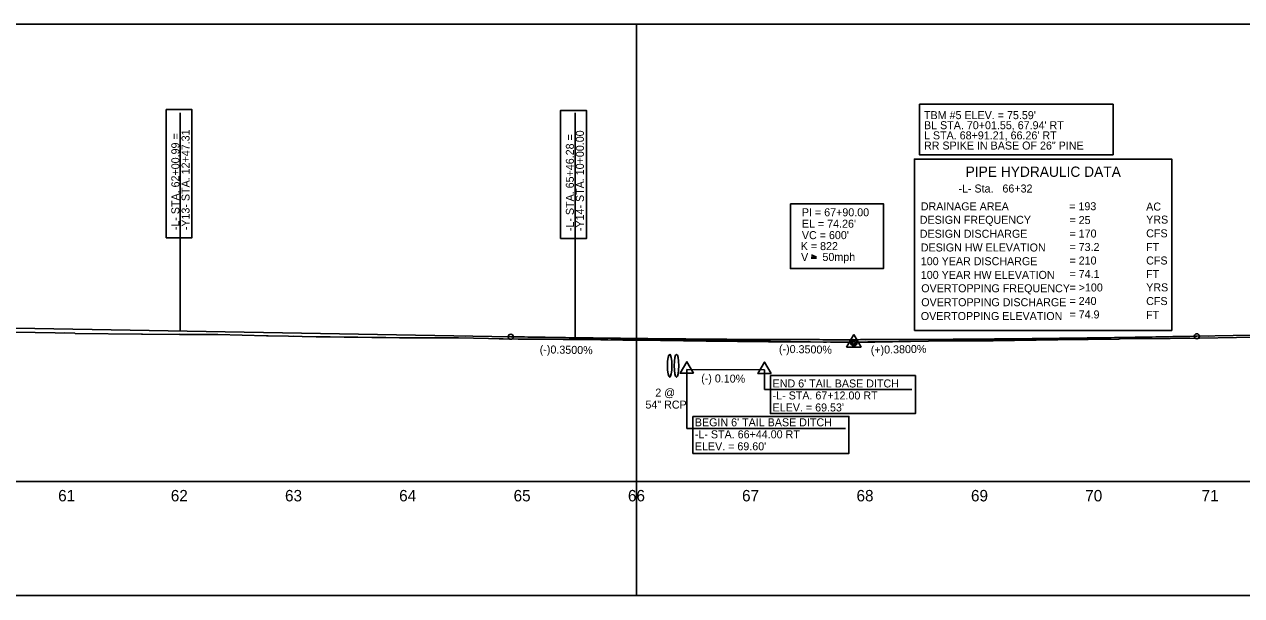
# Model space of a CAD drawing. Extents: x 2366464 to 2375718, y 801842 to 804354.
# Drawn here: x 2372383 to 2373447, y 803754 to 804254 of the extents above; entities that cross this region are included whole.
import ezdxf

# ---------------------------------------------------------------- set-up
doc = ezdxf.new("R2010")
doc.units = 0
for name, color, linetype in [('Default', 7, 'Continuous'), ('Exist Profile Cell', 7, 'Continuous'), ('Exist Vertical Profile Ground Line', 7, 'Continuous'), ('Exist Vertical Profile Horizontal Axis Label Major', 7, 'Continuous'), ('Prop Grid Mask', 7, 'Continuous'), ('Prop PFL VPI Symbol CELL', 7, 'Continuous'), ('Prop Vertical Profile Curve Label', 7, 'Continuous'), ('Prop Vertical Profile Ditch Grade Right', 7, 'Continuous'), ('Prop Vertical Profile Ditch Grade Right Label', 7, 'Continuous'), ('Prop Vertical Profile Grade', 7, 'Continuous'), ('Prop Vertical Profile Grade Label', 7, 'Continuous'), ('Prop VPI Label', 7, 'Continuous'), ('Scratch_Level_5', 7, 'Continuous'), ('Sheet Layout Profile Border Port 1', 7, 'Continuous'), ('Sheet Layout Profile Border Port 2', 7, 'Continuous')]:
    doc.layers.add(name, color=color, linetype=linetype)

# ---------------------------------------------------------------- blocks, each defined once
blk = doc.blocks.new('Profile VPI Symbol')
at = {"layer": 'Prop PFL VPI Symbol CELL'}
for p, q in [((-0.001, 0.147), (-0.13, -0.077)), ((-0.001, 0.147), (0.129, -0.077)), ((-0.13, -0.077), (0.129, -0.077))]:
    blk.add_line(p, q, dxfattribs=at)
for radius in [0.035, 0.024]:
    blk.add_circle((-0.001, -0.003), radius, dxfattribs=at)

msp = doc.modelspace()

# ---------------------------------------------------------------- linework, layer by layer
at = {"layer": 'Default'}
for centre in [(2372947, 803955.2), (2372953, 803955.2)]:
    msp.add_ellipse(centre, major_axis=(0, 10), ratio=0.2, dxfattribs=at)
at = {"layer": 'Exist Profile Cell'}
msp.add_line((2367318, 803854), (2374481.8, 803854), dxfattribs=at)
at = {"layer": 'Exist Vertical Profile Ground Line'}
for points in [[(2372374.8, 803984.6), (2372426.7, 803983.6), (2372427.2, 803983.5), (2372485.2, 803982.9), (2372485.9, 803982.9), (2372518.4, 803982.6), (2372551.5, 803982.4), (2372551.9, 803982.4), (2372594.5, 803981.5), (2372595.8, 803981.5), (2372613.5, 803981.1), (2372625.7, 803980.8), (2372637.8, 803980.6), (2372642.5, 803980.5), (2372644.5, 803980.5), (2372650, 803980.4), (2372662.2, 803980.2), (2372674.3, 803980.1), (2372686.5, 803979.9), (2372696.1, 803979.8), (2372697.1, 803979.8), (2372698.7, 803979.8), (2372710.8, 803979.7), (2372723, 803979.7), (2372736.1, 803979.7), (2372748.3, 803979.7), (2372749.2, 803979.7), (2372750, 803979.7), (2372762.2, 803979.5), (2372775.3, 803979.2), (2372788.4, 803979), (2372797.8, 803978.8), (2372801.5, 803978.8)], [(2372801.5, 803978.8), (2372814.5, 803978.6), (2372826.6, 803978.5), (2372827.2, 803978.5), (2372827.6, 803978.5), (2372840.7, 803978.4), (2372853.8, 803978.3), (2372866.8, 803978.2), (2372879.9, 803978.1), (2372886.8, 803978), (2372888.8, 803978), (2372891.8, 803977.9), (2372893, 803977.9), (2372906.1, 803977.7), (2372919.1, 803977.5), (2372978.8, 803976.7), (2373033.4, 803976.2), (2373034.2, 803976.2), (2373081.6, 803975.9), (2373082.8, 803975.9), (2373084.2, 803975.9), (2373120.3, 803976.1), (2373120.7, 803976.1), (2373121.2, 803976.1), (2373173.3, 803976.7), (2373228.3, 803977.1), (2373229.4, 803977.1), (2373229.8, 803977.1), (2373286.1, 803978), (2373286.5, 803978), (2373339.7, 803978.6), (2373341, 803978.7), (2373384.7, 803979.1), (2373410.2, 803979.3), (2373442.8, 803980), (2373469.6, 803980.6)]]:
    msp.add_lwpolyline(points, dxfattribs=at)
at = {"layer": 'Prop Grid Mask'}
for points in [[(2373165.4, 804184.1), (2373334.8, 804184.1), (2373334.8, 804139.9), (2373165.4, 804139.9)], [(2372506.7, 804067.2), (2372506.7, 804179.4), (2372529.2, 804179.4), (2372529.2, 804067.2)], [(2372851.6, 804066.5), (2372851.6, 804178.6), (2372874.2, 804178.6), (2372874.2, 804066.5)], [(2373161, 803986.1), (2373386, 803986.1), (2373386, 804136.1), (2373161, 804136.1)], [(2373052.6, 804097), (2373133.9, 804097), (2373133.9, 804040.3), (2373052.6, 804040.3)], [(2373035.1, 803946.6), (2373161.9, 803946.6), (2373161.9, 803913.4), (2373035.1, 803913.4)], [(2372967.3, 803910.9), (2373103.7, 803910.9), (2373103.7, 803878.5), (2372967.3, 803878.5)]]:
    msp.add_lwpolyline(points, close=True, dxfattribs=at)
at = {"layer": 'Prop Vertical Profile Curve Label'}
for p, q in [((2373070.8, 804050.3), (2373075.5, 804050.3)), ((2373070.8, 804049.3), (2373075.5, 804049.3)), ((2373075.5, 804050.3), (2373070.9, 804052.3))]:
    msp.add_line(p, q, dxfattribs=at)
for centre in [(2372808, 803980.6), (2373408, 803981)]:
    msp.add_circle(centre, 2.25, dxfattribs=at)
at = {"layer": 'Prop Vertical Profile Ditch Grade Right'}
msp.add_line((2373030, 803951.6), (2372962, 803952), dxfattribs=at)
at = {"layer": 'Prop Vertical Profile Ditch Grade Right Label'}
for p, q in [((2372962, 803900.3), (2372962, 803952)), ((2373030, 803934.3), (2373030, 803951.6)), ((2373158.8, 803934.3), (2373030, 803934.3)), ((2373100.8, 803900.3), (2372962, 803900.3))]:
    msp.add_line(p, q, dxfattribs=at)
for points in [[(2372967.8, 803948.6), (2372962, 803958.7), (2372956.1, 803948.6)], [(2373035.8, 803948.3), (2373030, 803958.4), (2373024.1, 803948.3)]]:
    msp.add_lwpolyline(points, close=True, dxfattribs=at)
at = {"layer": 'Prop Vertical Profile Grade'}
for p, q in [((2372293, 803989.6), (2372808, 803980.6)), ((2373408, 803981), (2373488, 803982.5))]:
    msp.add_line(p, q, dxfattribs=at)
msp.add_spline([(2372808, 803980.6), (2372820, 803980.4), (2372832, 803980.2), (2372844, 803980), (2372856, 803979.8), (2372868, 803979.6), (2372880, 803979.5), (2372892, 803979.3), (2372904, 803979.2), (2372916, 803979), (2372928, 803978.9), (2372940, 803978.8), (2372952, 803978.7), (2372964, 803978.6), (2372976, 803978.5), (2372988, 803978.4), (2373000, 803978.3), (2373012, 803978.3), (2373024, 803978.2), (2373036, 803978.1), (2373048, 803978.1), (2373060, 803978.1), (2373072, 803978.1), (2373084, 803978), (2373096, 803978), (2373108, 803978), (2373120, 803978.1), (2373132, 803978.1), (2373144, 803978.1), (2373156, 803978.2), (2373168, 803978.2), (2373180, 803978.3), (2373192, 803978.3), (2373204, 803978.4), (2373216, 803978.5), (2373228, 803978.6), (2373240, 803978.7), (2373252, 803978.8), (2373264, 803978.9), (2373276, 803979), (2373288, 803979.2), (2373300, 803979.3), (2373312, 803979.5), (2373324, 803979.6), (2373336, 803979.8), (2373348, 803980), (2373360, 803980.2), (2373372, 803980.4), (2373384, 803980.6), (2373396, 803980.8), (2373408, 803981)], degree=3, dxfattribs=at)
at = {"layer": 'Prop VPI Label'}
for p, q in [((2372519, 803985.6), (2372519, 804176.4)), ((2372864.3, 803979.7), (2372864.3, 804176.4)), ((2372808, 803980.6), (2373105.2, 803975.4)), ((2373408, 803981), (2373110.7, 803975.4))]:
    msp.add_line(p, q, dxfattribs=at)
msp.add_circle((2373108, 803975.3), 2.75, dxfattribs=at)
at = {"layer": 'Scratch_Level_5'}
for p, q in [((2372418, 803984.5), (2372418, 803984.5)), ((2372518, 803983.3), (2372518, 803983.3)), ((2372518, 803983.3), (2372518, 803983.3)), ((2372518, 803983.3), (2372518, 803983.3)), ((2372618, 803981.7), (2372618, 803981.7)), ((2372768, 803980.4), (2372768, 803980.4)), ((2372868, 803979.5), (2372868, 803979.5)), ((2372918, 803978.9), (2372918, 803978.9)), ((2372968, 803978), (2372968, 803978)), ((2373018, 803977.5), (2373018, 803977.5)), ((2373068, 803977.2), (2373068, 803977.2)), ((2373118, 803977.2), (2373118, 803977.2)), ((2373168, 803977.9), (2373168, 803977.9)), ((2373218, 803978.5), (2373218, 803978.5)), ((2373268, 803978.8), (2373268, 803978.8)), ((2373318, 803979.5), (2373318, 803979.5)), ((2373368, 803980.2), (2373368, 803980.2)), ((2373418, 803980.6), (2373418, 803980.6))]:
    msp.add_line(p, q, dxfattribs=at)
at = {"layer": 'Sheet Layout Profile Border Port 1'}
msp.add_lwpolyline([(2372918, 803754), (2374318, 803754), (2374318, 804254), (2372918, 804254)], close=True, dxfattribs=at)
at = {"layer": 'Sheet Layout Profile Border Port 2'}
msp.add_lwpolyline([(2371518, 803754), (2372918, 803754), (2372918, 804254), (2371518, 804254)], close=True, dxfattribs=at)

# ---------------------------------------------------------------- block references
at = {"layer": 'Prop Grid Mask', "xscale": 50, "yscale": 50}
msp.add_blockref('Profile VPI Symbol', (2373108, 803975.3), dxfattribs=at)

# ---------------------------------------------------------------- texts
at = {"layer": 'Default'}
for s, height, p in [('PIPE HYDRAULIC DATA', 9, (2373205.8, 804120.5)), ('-L- Sta.   66+32', 7, (2373199.5, 804106.8)), ('DRAINAGE AREA', 7, (2373166.6, 804091.2)), ('= 193', 7, (2373296.4, 804091.3)), ('AC', 7, (2373363.7, 804091)), ('DESIGN FREQUENCY', 7, (2373165.7, 804079.4)), ('= 25', 7, (2373296.6, 804079.2)), ('YRS', 7, (2373363.7, 804079.6)), ('DESIGN DISCHARGE', 7, (2373165.7, 804067.2)), ('= 170', 7, (2373296.6, 804067.4)), ('CFS', 7, (2373363.7, 804067.6)), ('DESIGN HW ELEVATION', 7, (2373166.6, 804055.2)), ('= 73.2', 7, (2373296.6, 804055.6)), ('FT', 7, (2373363.7, 804055.6)), ('100 YEAR DISCHARGE', 7, (2373166.6, 804043.2)), ('= 210', 7, (2373296.6, 804043.8)), ('CFS', 7, (2373363.7, 804043.8)), ('100 YEAR HW ELEVATION', 7, (2373166.6, 804031.2)), ('= 74.1', 7, (2373296.6, 804032)), ('FT', 7, (2373363.7, 804032)), ('OVERTOPPING FREQUENCY', 7, (2373167, 804019.5)), ('= >100', 7, (2373296.6, 804020.2)), ('YRS', 7, (2373363.7, 804020.3)), ('OVERTOPPING DISCHARGE', 7, (2373167, 804007.3)), ('= 240', 7, (2373296.6, 804008.4)), ('CFS', 7, (2373363.7, 804008.3)), ('= 74.9', 7, (2373296.6, 803996.6)), ('FT', 7, (2373363.7, 803996.2)), ('OVERTOPPING ELEVATION', 7, (2373166.6, 803995.2)), ('2 @', 7, (2372934.4, 803928.2)), ('54" RCP', 7, (2372925.8, 803917.7))]:
    msp.add_text(s, height=height, dxfattribs=at).set_placement(p)
at = {"layer": 'Exist Vertical Profile Horizontal Axis Label Major'}
for s, p in [('61', (2372412.2, 803836.5)), ('62', (2372510.7, 803836.5)), ('63', (2372610.6, 803836.5)), ('64', (2372710.4, 803836.5)), ('65', (2372810.5, 803836.5)), ('66', (2372910.5, 803836.5)), ('67', (2373010.3, 803836.5)), ('68', (2373110.4, 803836.5)), ('69', (2373210.5, 803836.5)), ('70', (2373310.4, 803836.5)), ('71', (2373412.2, 803836.5))]:
    msp.add_text(s, height=10, dxfattribs=at).set_placement(p)
at = {"layer": 'Prop Vertical Profile Curve Label'}
for s, p in [('-L- STA. 62+00.99 = ', (2372518.2, 804073.8)), ('-Y13- STA. 12+47.31', (2372527.1, 804073.8)), ('-L- STA. 65+46.28 = ', (2372863.2, 804073)), ('-Y14- STA. 10+00.00', (2372872, 804073))]:
    msp.add_text(s, height=7, rotation=90, dxfattribs=at).set_placement(p)
for s, p in [("VC = 600'", (2373062.6, 804066)), ('K = 822', (2373061.6, 804056.4)), ('V', (2373061.9, 804046.8)), ('50mph', (2373080.6, 804046.9))]:
    msp.add_text(s, height=7, dxfattribs=at).set_placement(p)
at = {"layer": 'Prop Vertical Profile Ditch Grade Right Label'}
msp.add_text('(-) 0.10%', height=7, rotation=359.2594, dxfattribs=at).set_placement((2372974.5, 803940.8))
for s, p in [("END 6' TAIL BASE DITCH", (2373037, 803936.2)), ('-L- STA. 67+12.00 RT', (2373037, 803925.7)), ("ELEV. = 69.53'", (2373037, 803915.2)), ("BEGIN 6' TAIL BASE DITCH", (2372969, 803902.2)), ('-L- STA. 66+44.00 RT', (2372969, 803891.7)), ("ELEV. = 69.60'", (2372969, 803881.2))]:
    msp.add_text(s, height=7, dxfattribs=at).set_placement(p)
at = {"layer": 'Prop Vertical Profile Grade Label'}
for s, rotation, p in [('(-)0.3500%', 358.9974, (2372833.3, 803966.1)), ('(-)0.3500%', 358.9974, (2373042.5, 803966.5)), ('(+)0.3800%', 1.0885, (2373122.9, 803965.6))]:
    msp.add_text(s, height=7, rotation=rotation, dxfattribs=at).set_placement(p)
at = {"layer": 'Prop VPI Label'}
for s, p in [("TBM #5 ELEV. = 75.59'", (2373169.4, 804171)), ("BL STA. 70+01.55, 67.94' RT", (2373169.4, 804162.2)), ("L STA. 68+91.21, 66.26' RT", (2373169.4, 804153.3)), ('RR SPIKE IN BASE OF 26" PINE', (2373169.4, 804144.4)), ('PI = 67+90.00', (2373062.6, 804086)), ("EL = 74.26'", (2373062.6, 804076))]:
    msp.add_text(s, height=7, dxfattribs=at).set_placement(p)

doc.saveas('drawing.dxf')
